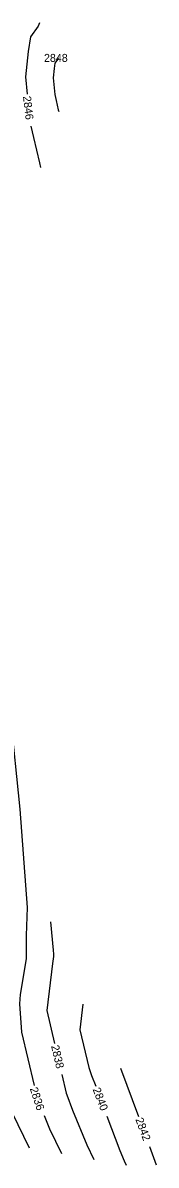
# Model space of a CAD drawing. Extents: x 1326424 to 1329294, y 1001359 to 1003823.
# Drawn here: x 1328536.8 to 1328570.2, y 1002748.1 to 1003033.5 of the extents above; entities that cross this region are included whole.
import ezdxf

# ---------------------------------------------------------------- set-up
doc = ezdxf.new("R2010")
doc.units = 0
doc.layers.add('Prop Rem of Exist Asph Pvmt', color=7, linetype='Continuous')
doc.layers.add('Scratch_Level_3', color=7, linetype='Continuous')

msp = doc.modelspace()

# ---------------------------------------------------------------- linework, layer by layer
at = {"layer": 'Prop Rem of Exist Asph Pvmt'}
for points in [[(1328551.87, 1002788.31), (1328551.11, 1002781.88), (1328553.32, 1002772.45), (1328554.04, 1002770.44), (1328555.05, 1002767.77)], [(1328557.88, 1002760.29), (1328561.12, 1002751.74), (1328562.18, 1002749.16), (1328562.71, 1002748.07)]]:
    msp.add_lwpolyline(points, dxfattribs=at)
at = {"layer": 'Scratch_Level_3'}
for points in [[(1328540.95, 1003033.48), (1328540.64, 1003032.67), (1328538.7, 1003030.02), (1328538.17, 1003026.3), (1328537.44, 1003019.96), (1328537.86, 1003015.62)], [(1328545.68, 1003024.72), (1328545.57, 1003024.42), (1328544.85, 1003023.43), (1328544.65, 1003022.05), (1328544.38, 1003019.7), (1328544.78, 1003015.54), (1328545.14, 1003014.09), (1328545.69, 1003011.73), (1328545.8, 1003011.3)], [(1328538.78, 1003007.68), (1328539.47, 1003004.84), (1328540.98, 1002998.49), (1328541.27, 1002997.32)], [(1328532.35, 1002867.18), (1328533.66, 1002860.65), (1328536.04, 1002837.02), (1328537.85, 1002812.47), (1328537.67, 1002805.48), (1328537.63, 1002799.64), (1328536.13, 1002790.74), (1328536, 1002788.39), (1328536.51, 1002781.29), (1328539.62, 1002768.01)], [(1328530.85, 1002811.07), (1328530.84, 1002810.5), (1328530.77, 1002799.05), (1328529.99, 1002794.46), (1328529.69, 1002788.98), (1328530.88, 1002772.38), (1328532.71, 1002764.56), (1328534.11, 1002761.15), (1328538.39, 1002752.39)], [(1328543.71, 1002808.89), (1328544.43, 1002801.78), (1328544.5, 1002800.76), (1328544.5, 1002800.47), (1328544.49, 1002800.23), (1328544.2, 1002798.46), (1328542.81, 1002786.73), (1328544.74, 1002778.51)], [(1328561.31, 1002772.31), (1328565.76, 1002760.24)], [(1328546.57, 1002770.72), (1328547.66, 1002766.07), (1328547.81, 1002765.66), (1328549.27, 1002761.8), (1328552.82, 1002753.16), (1328554.6, 1002749.51)], [(1328542.12, 1002760.44), (1328543.47, 1002757.15), (1328546.5, 1002750.95)], [(1328568.53, 1002752.74), (1328570.21, 1002748.18)]]:
    msp.add_lwpolyline(points, dxfattribs=at)

# ---------------------------------------------------------------- texts
at = {"layer": 'Prop Rem of Exist Asph Pvmt'}
msp.add_text('2840', height=2, rotation=290.7308, dxfattribs=at).set_placement((1328554.26, 1002767.03))
at = {"layer": 'Scratch_Level_3'}
msp.add_text('2848', height=2, dxfattribs=at).set_placement((1328542.1, 1003023.72))
for s, rotation, p in [('2846', 276.6431, (1328536.84, 1003015.08)), ('2838', 283.1944, (1328543.87, 1002777.84)), ('2836', 288.2124, (1328538.53, 1002767.2)), ('2842', 290.2534, (1328564.97, 1002759.51))]:
    msp.add_text(s, height=2, rotation=rotation, dxfattribs=at).set_placement(p)

doc.saveas('drawing.dxf')
